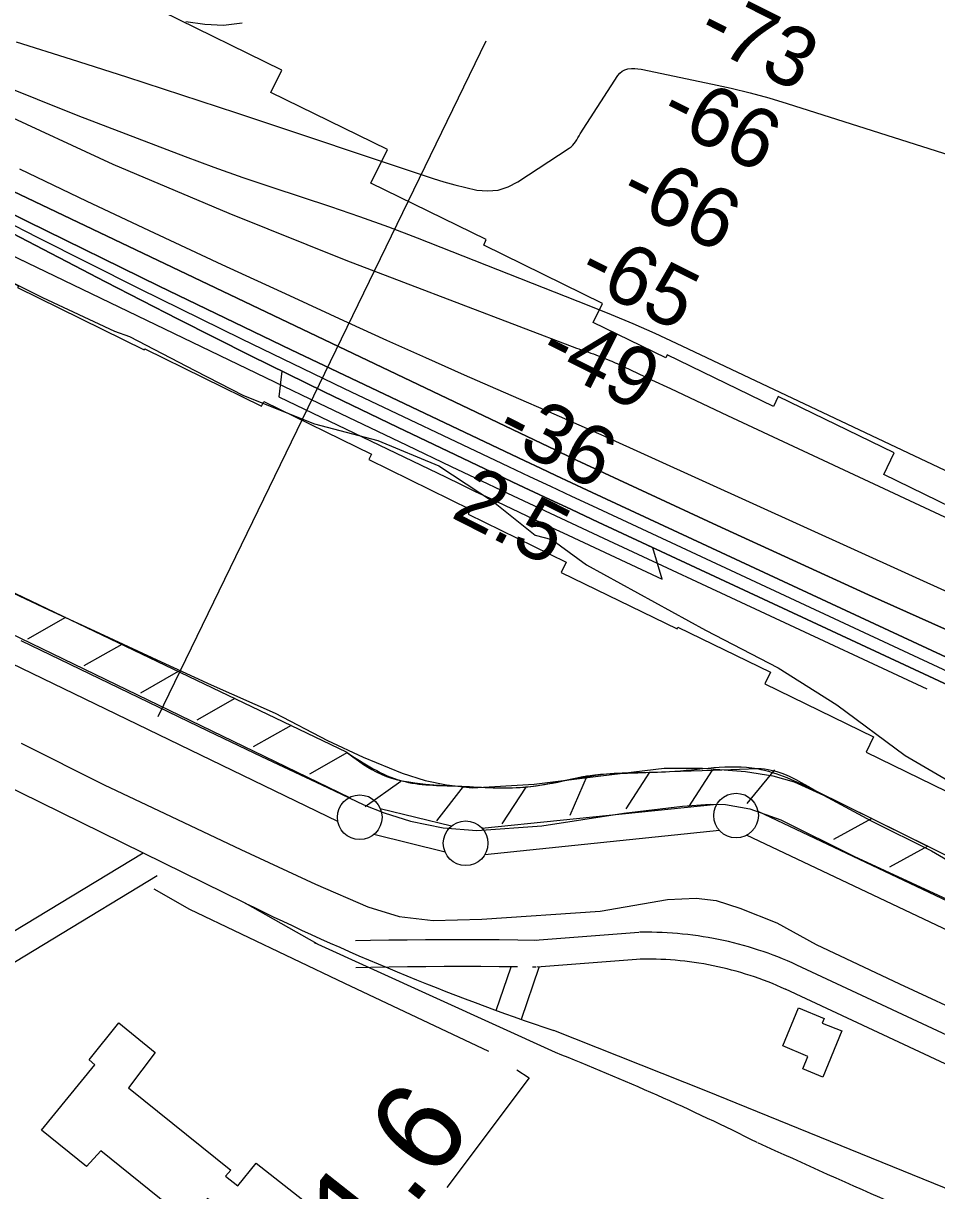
# Model space of a CAD drawing. Extents: x 3567028 to 3605064, y 510945 to 536587.
# Drawn here: x 3582639 to 3583661, y 524363 to 525671 of the extents above; entities that cross this region are included whole.
import ezdxf

# ---------------------------------------------------------------- set-up
doc = ezdxf.new("R2010")
doc.units = 0
for name, color, linetype in [('V-BLDG-OTLN', 7, 'Continuous'), ('V-FLOD-BASE', 7, 'Continuous'), ('V-LEVE-TOET', 7, 'Continuous'), ('V-RIVR-EDGE', 7, 'Continuous'), ('V-RIVR-RANG', 7, 'Continuous'), ('V-ROAD-CNTR', 7, 'Continuous'), ('V-RRAP-FSHR', 7, 'Continuous'), ('V-RRAP-RVMT', 7, 'Continuous'), ('V-SURV-IDEN', 7, 'Continuous'), ('V-SURV-LINE', 7, 'Continuous'), ('V-TOPO-DPTH', 7, 'Continuous'), ('V-TOPO-MAJR', 7, 'Continuous'), ('V-TOPO-MINR', 7, 'Continuous'), ('V-TOPO-SHOR', 7, 'Continuous'), ('V-TOPO-WATR', 7, 'Continuous')]:
    doc.layers.add(name, color=color, linetype=linetype)

msp = doc.modelspace()

# ---------------------------------------------------------------- linework, layer by layer
at = {"layer": 'V-BLDG-OTLN'}
for points in [[(3583555.2, 524542.2), (3583533.9, 524490.5), (3583511.6, 524499.7), (3583517.3, 524513.5), (3583489.1, 524525.3), (3583506.9, 524568), (3583535.5, 524556.1), (3583533.3, 524551)], [(3582951.6, 524353.1), (3582875.3, 524258), (3582824.5, 524298.4), (3582858.9, 524342.7), (3582844.9, 524354.5), (3582824, 524328.5), (3582725.3, 524407.8), (3582709.3, 524390.5), (3582658.9, 524431), (3582718.9, 524504.3), (3582712.3, 524509.8), (3582745.6, 524551.1), (3582786.2, 524518), (3582756.5, 524478.4), (3582871.2, 524386.4), (3582865.1, 524379.4), (3582878.8, 524368.6), (3582899.3, 524393.9)]]:
    msp.add_lwpolyline(points, close=True, dxfattribs=at)
at = {"layer": 'V-FLOD-BASE'}
msp.add_lwpolyline([(3582636, 524979.5), (3582745.7, 524926.5), (3582845.4, 524878.1), (3582905.5, 524849.5), (3582979.1, 524814.8), (3583020.1, 524795.5), (3583042.7, 524786.3), (3583072.3, 524777), (3583108.9, 524769.7), (3583146.6, 524766.5), (3583219.4, 524772), (3583311, 524785.9), (3583376.9, 524794), (3583408, 524796.3), (3583425.1, 524795.7), (3583452.2, 524791), (3583486.8, 524778.7), (3583568.9, 524737.9), (3583668.1, 524692), (3583770.3, 524643.6), (3583796.8, 524630.4)], dxfattribs=at)
at = {"layer": 'V-LEVE-TOET'}
for points in [[(3582587.1, 525051.6), (3582667.3, 525013.8), (3582718.4, 524990.4), (3582788, 524957.7), (3582849.1, 524929.7), (3582920.7, 524898), (3582979.3, 524867.5), (3583019.4, 524848.6), (3583063, 524830.8), (3583088.5, 524822.5), (3583112.6, 524817.8), (3583141.2, 524814.6), (3583210.6, 524818.7), (3583285.5, 524827.7), (3583356.4, 524836.3), (3583399.1, 524836.5), (3583447.3, 524832.6), (3583478, 524827.9), (3583502, 524821.2), (3583534.6, 524806.4), (3583588.1, 524777.4), (3583655.7, 524743.8), (3583718.3, 524707.2)], [(3582636.3, 524864.5), (3582729, 524817.7), (3582797.1, 524785.5), (3582882.2, 524745.3), (3582965.8, 524706.5), (3583024.5, 524681), (3583059.6, 524670.2), (3583097.7, 524665.9), (3583152, 524667.5), (3583284.7, 524676.2), (3583360.2, 524689.2), (3583392.3, 524691), (3583414.4, 524688.3), (3583441, 524679.6), (3583482.6, 524663.3), (3583526.6, 524638.8), (3583619.8, 524595), (3583706.9, 524554.7), (3583788.6, 524519.5), (3583869.7, 524483.7), (3584060.5, 524384.5), (3584180.2, 524328.9)]]:
    msp.add_lwpolyline(points, dxfattribs=at)
at = {"layer": 'V-RIVR-EDGE'}
msp.add_lwpolyline([(3582612.9, 525387), (3582660.3, 525363.5), (3582740.6, 525326), (3582757.4, 525320), (3582830.6, 525282), (3582885.1, 525253.7), (3582964.9, 525222.2), (3583035.7, 525203.5), (3583104.1, 525175.1), (3583165.2, 525134.7), (3583211.9, 525097.4), (3583230.5, 525092.5), (3583269.5, 525064.2), (3583402.6, 524991.2), (3583484.1, 524949), (3583549.5, 524907.4), (3583626.2, 524850.8), (3583702.3, 524806.2)], dxfattribs=at)
at = {"layer": 'V-RIVR-RANG'}
msp.add_line((3582789.7, 524894.3), (3583156.9, 525650.9), dxfattribs=at)
at = {"layer": 'V-ROAD-CNTR'}
for points in [[(3582887, 524685.4), (3582497.5, 524876.8), (3582412.6, 524911.1), (3582105.6, 525059.8), (3581875.8, 525171.8), (3581500.5, 525353.1), (3581352.7, 525420.9), (3581223.3, 525485.8)], [(3582772.9, 524741.4), (3582534.1, 524596.8), (3582289.4, 524287.3)], [(3582788.5, 524715.7), (3582554.3, 524574), (3582312.9, 524268.7)], [(3582967.6, 524639.6), (3582887, 524685.4)], [(3583234.5, 524518), (3582964.8, 524640.9)], [(3583213, 524643.6), (3583192.4, 524643.9), (3583171.7, 524644.1), (3583151.1, 524644.3), (3583130.5, 524644.3), (3583109.8, 524644.3), (3583089.2, 524644.1), (3583068.5, 524644), (3583047.9, 524643.7), (3583027.3, 524643.3), (3583010.5, 524643)], [(3583328, 524652.5), (3583211.6, 524643.6)], [(3583504.8, 524616), (3583499.6, 524618.4), (3583494.3, 524620.7), (3583488.9, 524622.9), (3583483.6, 524625), (3583478.2, 524627.1), (3583472.7, 524629.1), (3583467.3, 524631), (3583461.8, 524632.8), (3583456.3, 524634.6), (3583450.7, 524636.3), (3583445.2, 524637.9), (3583439.6, 524639.4), (3583434, 524640.8), (3583428.4, 524642.2), (3583422.7, 524643.4), (3583417.1, 524644.6), (3583411.4, 524645.7), (3583405.7, 524646.7), (3583400, 524647.7), (3583394.3, 524648.6), (3583388.5, 524649.3), (3583382.8, 524650), (3583377, 524650.7), (3583371.3, 524651.2), (3583365.5, 524651.6), (3583359.7, 524652), (3583354, 524652.3), (3583348.2, 524652.5), (3583342.4, 524652.6), (3583336.6, 524652.6), (3583330.9, 524652.6), (3583328.8, 524652.6)], [(3583192, 524613.9), (3583192, 524613.9), (3583171.5, 524614.1), (3583151, 524614.3), (3583130.4, 524614.3), (3583109.9, 524614.3), (3583089.4, 524614.1), (3583068.9, 524614), (3583048.4, 524613.7), (3583027.8, 524613.3), (3583011.2, 524613)], [(3583168.1, 524564.9), (3583184.8, 524614)], [(3583196.5, 524555.2), (3583216.4, 524613.6)], [(3583212.6, 524613.6), (3583208.7, 524613.7)], [(3583330.3, 524622.6), (3583213.9, 524613.7)], [(3583492.5, 524588.7), (3583487.5, 524590.9), (3583482.6, 524593.1), (3583477.6, 524595.1), (3583472.7, 524597.1), (3583467.6, 524599), (3583462.6, 524600.8), (3583457.6, 524602.6), (3583452.5, 524604.3), (3583447.4, 524605.9), (3583442.3, 524607.5), (3583437.1, 524609), (3583431.9, 524610.4), (3583426.8, 524611.7), (3583421.6, 524612.9), (3583416.3, 524614.1), (3583411.1, 524615.2), (3583405.8, 524616.2), (3583400.6, 524617.2), (3583395.3, 524618.1), (3583390, 524618.9), (3583384.7, 524619.6), (3583379.4, 524620.2), (3583374.1, 524620.8), (3583368.7, 524621.3), (3583363.4, 524621.7), (3583358, 524622.1), (3583352.7, 524622.3), (3583347.3, 524622.5), (3583342, 524622.6), (3583336.6, 524622.6), (3583331.2, 524622.6), (3583329.4, 524622.6)], [(3583932.1, 524416.3), (3583505, 524616)], [(3583919.4, 524389.1), (3583492.3, 524588.8)], [(3583841.8, 524297.7), (3583786.1, 524319.5), (3583403.1, 524475), (3583232.7, 524542.5)]]:
    msp.add_lwpolyline(points, dxfattribs=at)
for centre, radius, start, end in [((3584127.6, 527196.6), 2800.9, 243.7093, 251.3673), ((3582229.2, 521961.3), 2747.2, 63.3741, 68.5346), ((3587777.1, 533838.2), 10362.6, 245.3855, 247.27911)]:
    msp.add_arc(centre, radius, start, end, dxfattribs=at)
at = {"layer": 'V-RRAP-FSHR'}
for p, q in [((3582686, 525005.1), (3582643.4, 524981.1)), ((3582749.1, 524974.8), (3582706.5, 524950.9)), ((3582812.2, 524944.6), (3582769.7, 524920.6)), ((3582875.4, 524914.4), (3582832.8, 524890.4)), ((3582938.5, 524884.1), (3582895.9, 524860.2)), ((3583001.6, 524853.9), (3582959.1, 524829.9)), ((3583270.1, 524828.1), (3583250.7, 524783.3)), ((3583340, 524831.8), (3583313.5, 524790.8)), ((3583410, 524834.3), (3583383.4, 524793.3)), ((3583479.9, 524834.7), (3583449, 524796.9)), ((3583061.4, 524821.4), (3583021.5, 524793.3)), ((3583131.4, 524816.1), (3583101.5, 524777.5)), ((3583201.3, 524815.2), (3583174.7, 524774.2)), ((3583588.7, 524780), (3583545.9, 524756.5)), ((3583651.5, 524749), (3583608.7, 524725.5))]:
    msp.add_line(p, q, dxfattribs=at)
for points in [[(3581361.6, 525642.9), (3581677.8, 525489), (3582249.9, 525213.9), (3583000.2, 524854.6)], [(3583000.2, 524854.6), (3583007.5, 524849.1), (3583013.9, 524844.5), (3583019.5, 524840.7), (3583024.6, 524837.6), (3583029.1, 524835), (3583033, 524832.8), (3583040.1, 524829.4), (3583045.5, 524827.1), (3583049.7, 524825.6), (3583056, 524823.7), (3583062.5, 524822.3), (3583070.3, 524821), (3583077.2, 524820), (3583089.2, 524818.6), (3583098.2, 524817.9), (3583111.7, 524817), (3583125.2, 524816.4), (3583160.1, 524814.8), (3583177.6, 524814.5), (3583186.3, 524814.6), (3583195, 524814.9), (3583201.1, 524815.3), (3583212.4, 524816.7), (3583222.3, 524818.3), (3583256.8, 524825.4), (3583265.4, 524827), (3583278.5, 524828.9), (3583285, 524829.6), (3583291.6, 524830), (3583326.9, 524831.3), (3583362.2, 524832.6), (3583411.3, 524834.3), (3583460.4, 524835.9), (3583464.8, 524835.9), (3583468.8, 524835.6), (3583472.6, 524835), (3583476.1, 524834.4), (3583482.5, 524832.7), (3583488.1, 524830.8), (3583493, 524828.9), (3583497.2, 524827), (3583504.5, 524823.4), (3583509.9, 524820.5), (3583518, 524815.8), (3583526, 524811)], [(3583526, 524811), (3583813.2, 524669.1), (3583798.5, 524635)], [(3583526, 524811), (3583807.6, 524671.9)]]:
    msp.add_lwpolyline(points, dxfattribs=at)
msp.add_spline([(3583000.2, 524854.6), (3583062.5, 524822.3), (3583125.2, 524816.4), (3583195, 524814.9), (3583291.6, 524830), (3583362.2, 524832.6), (3583460.4, 524835.9), (3583526, 524811)], degree=3, dxfattribs=at)
at = {"layer": 'V-RRAP-RVMT'}
for points in [[(3583276.7, 525335.5), (3583287.2, 525357), (3583154.2, 525422.3), (3583157.1, 525428.4), (3583028, 525491.6), (3583046.6, 525529.3), (3582915.9, 525593.3), (3582928.1, 525618.2), (3582794.1, 525684), (3582804.7, 525705.3), (3582671.6, 525770.7), (3582676.2, 525780), (3582534.3, 525849.8), (3582526.1, 525833.2), (3582398.8, 525895.9), (3582388.3, 525874.4), (3582253.7, 525940.6), (3582244.3, 525921.4), (3582129.1, 525978.2), (3582136.4, 525993.1), (3582082.4, 526019.6)], [(3581824.7, 525751.2), (3581834.6, 525735.2), (3581842.5, 525740), (3581888.8, 525711), (3581892.6, 525716.9), (3581966.2, 525680.6), (3581958.9, 525665.8), (3582101.3, 525595.8), (3582107.4, 525608.1), (3582235.5, 525545.1), (3582246.1, 525566.6), (3582380.6, 525500.4), (3582383.8, 525506.9), (3582502.3, 525448.6), (3582499.3, 525442.6), (3582633.3, 525376.7), (3582632.3, 525374.8), (3582774.1, 525305), (3582774.7, 525306.2), (3582905.3, 525242), (3582907.9, 525247.3), (3583028.4, 525188), (3583025.4, 525182), (3583139.4, 525126)], [(3584443.1, 524807.6), (3584323.1, 524863.5), (3584325, 524867.8), (3584195.5, 524928.2), (3584190.8, 524918), (3584071.6, 524973.6), (3584068.4, 524966.9), (3583962.9, 525016), (3583969.6, 525030.2), (3583839.1, 525090.9), (3583834.2, 525080.5), (3583719.7, 525136.3), (3583708.7, 525113.5), (3583602.3, 525165.4), (3583614, 525189.5), (3583484.1, 525252.8), (3583478.6, 525241.5), (3583359.7, 525299.4), (3583358, 525295.9), (3583276.7, 525335.5)], [(3583139.4, 525126), (3583136.9, 525120.8), (3583246.7, 525067.2), (3583241, 525055.7), (3583370.8, 524992.5), (3583371.8, 524994.5), (3583475.3, 524944.1), (3583468.9, 524930.9), (3583590.9, 524871.5), (3583582.4, 524854.3), (3583701.9, 524796.1), (3583700.2, 524792.5), (3583830.6, 524731.8), (3583835.4, 524741.8), (3583953, 524687.1), (3583964.9, 524712.2), (3584082.4, 524657.7), (3584084.3, 524661.8), (3584203.3, 524606.4), (3584204.5, 524608.9), (3584311.7, 524559.1), (3584309.8, 524554.9), (3584440.4, 524496.9)]]:
    msp.add_lwpolyline(points, dxfattribs=at)
at = {"layer": 'V-SURV-LINE'}
for points in [[(3581244.7, 525655.4), (3583004, 524803.7)], [(3582990.9, 524776.7), (3581231.7, 525628.4)], [(3583038.4, 524791.3), (3583118.2, 524771.7)], [(3583152.3, 524769.3), (3583415.3, 524796.3)], [(3583461.2, 524788.4), (3585445.1, 523848.8)], [(3583111, 524742.5), (3583031.2, 524762.1)], [(3583418.4, 524766.5), (3583155.4, 524739.4)], [(3585432.2, 523821.6), (3583448.4, 524761.3)]]:
    msp.add_lwpolyline(points, dxfattribs=at)
for centre in [(3583015.4, 524781.5), (3583436.8, 524783.4), (3583134, 524752.3)]:
    msp.add_circle(centre, 25, dxfattribs=at)
at = {"layer": 'V-TOPO-DPTH'}
for points in [[(3584192.1, 524718.7), (3583946.9, 524802.3), (3583282.3, 525112.1), (3583252.5, 525126), (3583222.8, 525139.9), (3583193.1, 525153.9), (3583163.4, 525168), (3583057.7, 525218.2), (3582975.5, 525257.8), (3582893.5, 525298.1), (3582812, 525339.3), (3582730.8, 525381.1), (3581972.3, 525776.9), (3581945, 525791.5), (3581917.9, 525806.5), (3581891.1, 525822.1), (3581864.5, 525838), (3581261, 526209.4)], [(3581490.6, 526090.3), (3581635, 525999.7), (3581885.9, 525844.1), (3581905.5, 525832.3), (3581925.2, 525820.8), (3581945.2, 525809.7), (3581965.3, 525798.9), (3582351, 525597.7), (3582496.9, 525522.6), (3582643.4, 525448.6), (3582790.7, 525376.3), (3582938.6, 525305), (3583200.4, 525180.7), (3583217.8, 525172.4), (3583235.1, 525164.3), (3583252.5, 525156.1), (3583269.9, 525148), (3584192.1, 524718.7)], [(3584348.9, 524647.4), (3584309.6, 524665), (3584270.3, 524682.7), (3584231.2, 524700.6), (3584192.1, 524718.7), (3583269.9, 525148), (3583252.5, 525156.1), (3583235.1, 525164.3), (3583217.8, 525172.4), (3583200.4, 525180.7), (3582938.6, 525305), (3582790.7, 525376.3), (3582643.4, 525448.6), (3582496.9, 525522.6), (3582351, 525597.7), (3581965.3, 525798.9), (3581945.2, 525809.7), (3581925.2, 525820.8), (3581905.5, 525832.3), (3581885.9, 525844.1), (3581635, 525999.7), (3581490.6, 526090.3)], [(3582634.3, 525507.6), (3582709.7, 525471.6), (3582785.2, 525436), (3582861, 525400.7), (3582936.8, 525365.7), (3583002.1, 525335.7), (3583045.4, 525316), (3583088.9, 525296.4), (3583132.4, 525277.1), (3583176, 525258), (3583241.2, 525229.6), (3583252.3, 525224.8), (3583263.3, 525219.9), (3583274.3, 525215), (3583285.4, 525210), (3583682.5, 525030), (3583811.5, 524971.6), (3583940.6, 524913.4), (3584069.8, 524855.4), (3584199, 524797.6), (3584443.5, 524688.3)], [(3582634.3, 525507.6), (3582709.7, 525471.6), (3582785.2, 525436), (3582861, 525400.7), (3582936.8, 525365.7), (3583002.1, 525335.7), (3583045.4, 525316), (3583088.9, 525296.4), (3583132.4, 525277.1), (3583176, 525258), (3583241.2, 525229.6), (3583252.3, 525224.8), (3583263.3, 525219.9), (3583274.3, 525215), (3583285.4, 525210), (3583682.5, 525030), (3583811.5, 524971.6), (3583940.6, 524913.4), (3584069.8, 524855.4), (3584199, 524797.6), (3584443.5, 524688.3)], [(3582626.9, 525482.6), (3583234.9, 525192.5), (3583240.8, 525189.7), (3583246.6, 525186.9), (3583252.5, 525184.2), (3583258.3, 525181.4), (3583415.7, 525108.4), (3583500.4, 525069.3), (3583585.2, 525030.6), (3583670.2, 524992.4), (3583755.4, 524954.5), (3584398, 524670.4)], [(3584398, 524670.4), (3583755.4, 524954.5), (3583670.2, 524992.4), (3583585.2, 525030.6), (3583500.4, 525069.3), (3583415.7, 525108.4), (3583258.3, 525181.4), (3583252.5, 525184.2), (3583246.6, 525186.9), (3583240.8, 525189.7), (3583234.9, 525192.5), (3582626.9, 525482.6)], [(3582928.3, 525281), (3582924.9, 525252.3), (3583112, 525162.2), (3583128.3, 525154.4), (3583144.7, 525146.5), (3583161.1, 525138.7), (3583177.5, 525130.9), (3583193.9, 525123.1), (3583210.4, 525115.4), (3583226.8, 525107.6), (3583243.2, 525100), (3583354.2, 525048.2), (3583343.7, 525083.4)], [(3583343.7, 525083.4), (3583282.3, 525112.1), (3583252.5, 525126), (3583222.8, 525139.9), (3583193.1, 525153.9), (3583163.4, 525168), (3583057.7, 525218.2), (3582975.5, 525257.8), (3582928.3, 525281)]]:
    msp.add_lwpolyline(points, dxfattribs=at)
at = {"layer": 'V-TOPO-MAJR'}
msp.add_lwpolyline([(3582611.1, 525572.1), (3582739, 525512.9), (3582868.7, 525457.9), (3582999.7, 525405.5), (3583258, 525307), (3583260.7, 525306), (3583263.4, 525305.1), (3583266.1, 525304.1), (3583268.9, 525303.2), (3583271.6, 525302.3), (3583274.3, 525301.4), (3583277, 525300.4), (3583279.7, 525299.4), (3583295.5, 525293.2), (3583297.6, 525292.3), (3583301.6, 525290.6), (3583303.6, 525289.7), (3583342.2, 525271.5), (3583363.5, 525261.5), (3583384.8, 525251.5), (3583406.1, 525241.6), (3583427.4, 525231.6), (3584433.8, 524761.6)], dxfattribs=at)
at = {"layer": 'V-TOPO-MINR'}
for points in [[(3581437.7, 526264.7), (3581542.9, 526191.9), (3581649.3, 526120.9), (3581756.7, 526051.1), (3581938.2, 525935.4), (3581955.5, 525924.7), (3581973, 525914.4), (3581990.9, 525904.5), (3582008.9, 525895), (3582339.5, 525726.9), (3582428, 525683.7), (3582517.5, 525642.3), (3582608.2, 525603.9), (3582699.7, 525567.3), (3582819.7, 525521.7), (3582852, 525509.7), (3582884.5, 525498.1), (3582917.1, 525487.1), (3582949.9, 525476.4), (3582982.6, 525465.7), (3583015.2, 525454.5), (3583047.6, 525442.6)], [(3581261, 526209.4), (3581864.5, 525838), (3581891.1, 525822.1), (3581917.9, 525806.5), (3581945, 525791.5), (3581972.3, 525776.9), (3582730.8, 525381.1), (3582812, 525339.3), (3582893.5, 525298.1), (3582975.5, 525257.8), (3583057.7, 525218.2), (3583163.4, 525168), (3583193.1, 525153.9), (3583222.8, 525139.9), (3583252.5, 525126), (3583282.3, 525112.1), (3583946.9, 524802.3)], [(3581456.9, 526099.5), (3581875.2, 525841.1), (3581898.3, 525827.2), (3581921.5, 525813.6), (3581945.1, 525800.6), (3581968.8, 525787.9), (3582540.6, 525489.5), (3582654.3, 525431.1), (3582768.3, 525373.5), (3582883, 525317.2), (3582998.1, 525261.7), (3583182.1, 525174.4), (3583205.5, 525163.3), (3583229, 525152.2), (3583252.5, 525141.2), (3583276, 525130.2), (3584243.3, 524679.3)], [(3581490.6, 526090.3), (3581635, 525999.7), (3581885.9, 525844.1), (3581905.5, 525832.3), (3581925.2, 525820.8), (3581945.2, 525809.7), (3581965.3, 525798.9), (3582351, 525597.7), (3582496.9, 525522.6), (3582643.4, 525448.6), (3582790.7, 525376.3), (3582938.6, 525305), (3583200.4, 525180.7), (3583217.8, 525172.4), (3583235.1, 525164.3), (3583252.5, 525156.1), (3583269.9, 525148), (3584192.1, 524718.7), (3584231.2, 524700.6), (3584270.3, 524682.7), (3584309.6, 524665), (3584348.9, 524647.4)], [(3582820.6, 525672.8), (3582841.8, 525669.6), (3582862.8, 525668.7), (3582883.7, 525671.4)], [(3582630.6, 525649.8), (3582692.4, 525630.4), (3582754.1, 525610.7), (3582815.7, 525590.7), (3582877.2, 525570.4), (3583097.5, 525497), (3583109.6, 525493.2), (3583121.8, 525489.7), (3583134.1, 525486.7), (3583146.5, 525484), (3583158.6, 525483), (3583170.4, 525483.9), (3583181.6, 525487.5), (3583192.5, 525493), (3583250.1, 525531), (3583252.1, 525532.5), (3583254, 525534.2), (3583255.6, 525536.1), (3583257, 525538.1), (3583258.4, 525540.3), (3583259.7, 525542.5), (3583261.1, 525544.6), (3583262.4, 525546.8), (3583304.3, 525612.2), (3583306.6, 525614.9), (3583309.3, 525617.1), (3583312.4, 525618.6), (3583315.8, 525619.6), (3583319.6, 525620), (3583323.3, 525620), (3583327, 525619.7), (3583330.7, 525619.2), (3583410.3, 525602.7), (3583431.5, 525598), (3583452.5, 525592.9), (3583473.4, 525587.1), (3583494.1, 525580.8), (3583692.5, 525517.8)], [(3582355.5, 525540.9), (3582920, 525269.1), (3582969.4, 525245.3), (3583018.7, 525221.7), (3583068.2, 525198.1), (3583117.6, 525174.5), (3583144.8, 525161.6), (3583180.7, 525144.6), (3583216.6, 525127.7), (3583252.6, 525110.8), (3583288.5, 525094), (3583650.6, 524925.2)], [(3582634.3, 525507.6), (3582709.7, 525471.6), (3582785.2, 525436), (3582861, 525400.7), (3582936.8, 525365.7), (3583002.1, 525335.7), (3583045.4, 525316), (3583088.9, 525296.4), (3583132.4, 525277.1), (3583176, 525258), (3583241.2, 525229.6), (3583252.3, 525224.8), (3583263.3, 525219.9), (3583274.3, 525215), (3583285.4, 525210), (3583682.5, 525030), (3583811.5, 524971.6), (3583940.6, 524913.4), (3584069.8, 524855.4), (3584199, 524797.6), (3584443.5, 524688.3)], [(3582626.9, 525482.6), (3583234.9, 525192.5), (3583240.8, 525189.7), (3583246.6, 525186.9), (3583252.5, 525184.2), (3583258.3, 525181.4), (3583415.7, 525108.4), (3583500.4, 525069.3), (3583585.2, 525030.6), (3583670.2, 524992.4), (3583755.4, 524954.5), (3584398, 524670.4)], [(3583047.6, 525442.6), (3583079.8, 525430.4), (3583272.1, 525354.7), (3583296.8, 525344.7), (3583321.4, 525334.4), (3583345.7, 525323.6), (3583369.9, 525312.4), (3584210.1, 524915.1), (3584258.3, 524892.3), (3584306.4, 524869.6), (3584354.6, 524846.9)]]:
    msp.add_lwpolyline(points, dxfattribs=at)
at = {"layer": 'V-TOPO-SHOR'}
for p, q in [((3583191.3, 524498.6), (3583205, 524489.5)), ((3583205, 524489.5), (3583113, 524366.9))]:
    msp.add_line(p, q, dxfattribs=at)
msp.add_lwpolyline([(3582784.7, 524701.3), (3582824.9, 524678.4), (3582998.4, 524595.6), (3583159.6, 524519.6)], dxfattribs=at)
at = {"layer": 'V-TOPO-WATR'}
msp.add_lwpolyline([(3582924.9, 525252.3), (3583112, 525162.2), (3583128.3, 525154.4), (3583144.7, 525146.5), (3583161.1, 525138.7), (3583177.5, 525130.9), (3583193.9, 525123.1), (3583210.4, 525115.4), (3583226.8, 525107.6), (3583243.2, 525100), (3583354.2, 525048.2)], dxfattribs=at)

# ---------------------------------------------------------------- texts
at = {"layer": 'V-RIVR-RANG'}
for s, rotation, p in [('-73', 333.2779, (3583390, 525651.4)), ('-66', 333.2779, (3583348.1, 525560.6)), ('-66', 333.2779, (3583303, 525471.4)), ('-65', 333.2779, (3583256.4, 525382.9)), ('-49', 333.2779, (3583212.8, 525292.8)), ('-36', 333.2779, (3583164.1, 525205.4)), ('2.5', 332.9983, (3583115.9, 525118.2))]:
    msp.add_text(s, height=67, rotation=rotation, dxfattribs=at).set_placement(p)
at = {"layer": 'V-SURV-IDEN'}
msp.add_text('2886+91.6', height=100, rotation=51.7287, dxfattribs=at).set_placement((3582749.3, 523932.3))

doc.saveas('drawing.dxf')
